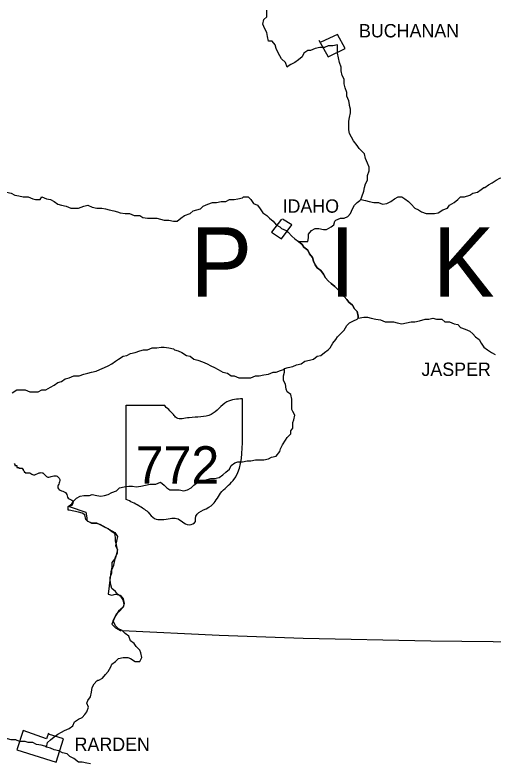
# Model space of a CAD drawing. Extents: x 0 to 40.2, y 0 to 22.
# Drawn here: x 5.119 to 5.818, y 17.238 to 18.331 of the extents above; entities that cross this region are included whole.
import ezdxf

# ---------------------------------------------------------------- set-up
doc = ezdxf.new("R2010")
doc.units = 0
doc.layers.add('Default', color=7, linetype='Continuous')
doc.layers.add('TR_Turning_Path1', color=7, linetype='Continuous')

msp = doc.modelspace()

# ---------------------------------------------------------------- linework, layer by layer
at = {"layer": 'Default'}
msp.add_line((5.2017, 17.6138), (5.1976, 17.6124), dxfattribs=at)
for points in [[(5.5167, 18.2546), (5.514, 18.2614), (5.5085, 18.2669), (5.5058, 18.271), (5.5031, 18.2764), (5.5003, 18.2819), (5.499, 18.2873), (5.4949, 18.2928), (5.4894, 18.2928), (5.4881, 18.2996), (5.4867, 18.3051), (5.484, 18.3105), (5.4812, 18.3173), (5.4826, 18.3241), (5.4867, 18.3282), (5.4867, 18.3351), (5.4867, 18.3378)], [(5.563, 18.2942), (5.5767, 18.2696), (5.6012, 18.2819), (5.5903, 18.3023), (5.5658, 18.2914)], [(5.5903, 18.2873), (5.5835, 18.286), (5.5767, 18.286), (5.5712, 18.2832), (5.5644, 18.2832), (5.5576, 18.2819), (5.5508, 18.2792), (5.5467, 18.2792), (5.5412, 18.2751), (5.5385, 18.2696), (5.533, 18.2655), (5.5276, 18.2614), (5.5221, 18.2587), (5.518, 18.256), (5.5167, 18.2546)], [(5.608, 18.2001), (5.6067, 18.2055), (5.6039, 18.2123), (5.6039, 18.2178), (5.6012, 18.2246), (5.5999, 18.2301), (5.5999, 18.2369), (5.5971, 18.2423), (5.5958, 18.2492), (5.5958, 18.2546), (5.593, 18.2614), (5.5917, 18.2682), (5.5903, 18.2751), (5.5903, 18.2792), (5.5903, 18.286), (5.5903, 18.2873)], [(5.6244, 18.061), (5.6258, 18.0651), (5.6285, 18.0733), (5.6299, 18.0787), (5.6312, 18.0842), (5.6339, 18.0896), (5.6339, 18.0965), (5.6367, 18.1033), (5.6367, 18.1087), (5.6339, 18.1142), (5.6312, 18.121), (5.6299, 18.1278), (5.6258, 18.1319), (5.6217, 18.136), (5.6189, 18.1401), (5.6135, 18.1469), (5.6108, 18.1524), (5.608, 18.1578), (5.6067, 18.1633), (5.6067, 18.1687), (5.6067, 18.1755), (5.608, 18.181), (5.6094, 18.1878), (5.6094, 18.1933), (5.608, 18.1987), (5.608, 18.1987), (5.608, 18.2001)], [(5.8057, 18.0787), (5.8112, 18.0828), (5.8166, 18.0855), (5.8221, 18.0896), (5.8275, 18.0924), (5.833, 18.0937), (5.8398, 18.0937), (5.8453, 18.0937), (5.8507, 18.091), (5.8575, 18.0896), (5.863, 18.091), (5.8657, 18.0924)], [(5.6244, 18.061), (5.6312, 18.0596), (5.6367, 18.0583), (5.6435, 18.0569), (5.6503, 18.0569), (5.6558, 18.0542), (5.6626, 18.0556), (5.668, 18.0583), (5.6735, 18.0624), (5.6789, 18.0651), (5.6844, 18.0651), (5.6885, 18.0624), (5.6939, 18.0583), (5.698, 18.0542), (5.7035, 18.0487), (5.7089, 18.046), (5.713, 18.0433), (5.7198, 18.0406), (5.7267, 18.0406), (5.7321, 18.0406), (5.7376, 18.0419), (5.7444, 18.046), (5.7512, 18.0487), (5.7539, 18.0528), (5.7607, 18.0569), (5.7662, 18.061), (5.7703, 18.0651), (5.7757, 18.0651), (5.7839, 18.0678), (5.788, 18.0706), (5.7948, 18.0719), (5.8003, 18.076), (5.8044, 18.0787), (5.8057, 18.0787), (5.8057, 18.0787)], [(5.0354, 18.0378), (5.0422, 18.0378), (5.0463, 18.0419), (5.0504, 18.046), (5.0572, 18.0487), (5.0613, 18.0542), (5.0668, 18.0583), (5.0722, 18.0624), (5.0763, 18.0665), (5.0804, 18.0706), (5.0872, 18.0733), (5.0927, 18.0746), (5.0995, 18.0733), (5.1063, 18.0719), (5.1131, 18.0706), (5.1186, 18.0678), (5.124, 18.0665), (5.1308, 18.0651), (5.1377, 18.0651), (5.1445, 18.0624), (5.1486, 18.061), (5.1554, 18.061), (5.1554, 18.061)], [(5.1554, 18.061), (5.1581, 18.0651), (5.1649, 18.0624), (5.1704, 18.061), (5.1758, 18.0583), (5.1813, 18.0542), (5.1867, 18.0528), (5.1936, 18.0515), (5.2004, 18.0487), (5.2058, 18.0487), (5.2113, 18.0487), (5.2195, 18.0515), (5.2249, 18.0528), (5.2317, 18.0501), (5.2385, 18.0487), (5.2454, 18.0487), (5.2508, 18.0474), (5.2563, 18.046), (5.2631, 18.0446), (5.2685, 18.0433), (5.2726, 18.0419), (5.2726, 18.0419)], [(5.2726, 18.0419), (5.2795, 18.0406), (5.2863, 18.0406), (5.2931, 18.0378), (5.3013, 18.0378), (5.3054, 18.0351), (5.3122, 18.0337), (5.319, 18.0337), (5.3258, 18.0337), (5.3313, 18.0324), (5.3367, 18.031), (5.3435, 18.031), (5.3503, 18.0296), (5.3558, 18.0296), (5.3613, 18.0337), (5.3667, 18.0378), (5.3749, 18.0406), (5.379, 18.0446), (5.3844, 18.046), (5.3899, 18.0474), (5.394, 18.0515), (5.4008, 18.0542), (5.4076, 18.0569), (5.4131, 18.0569), (5.4199, 18.0583), (5.4267, 18.0583), (5.4322, 18.061), (5.439, 18.061), (5.4444, 18.0624), (5.4512, 18.0637), (5.4526, 18.0651)], [(5.4526, 18.0651), (5.4594, 18.0651), (5.4635, 18.061), (5.4676, 18.0556), (5.4731, 18.0528), (5.4771, 18.0474), (5.4812, 18.0419), (5.4867, 18.0378), (5.4908, 18.0337), (5.4962, 18.0296), (5.5003, 18.0242), (5.5058, 18.0215), (5.5085, 18.0187), (5.5153, 18.016), (5.518, 18.0133), (5.5235, 18.0078), (5.5276, 18.0037), (5.533, 17.9997), (5.533, 17.9997), (5.533, 17.9997)], [(5.5876, 18.031), (5.5944, 18.0337), (5.5999, 18.0337), (5.6053, 18.0365), (5.6094, 18.0406), (5.6121, 18.0474), (5.6149, 18.0528), (5.6189, 18.0569), (5.623, 18.0596), (5.6244, 18.061)], [(5.5085, 18.0324), (5.4935, 18.0133), (5.5085, 18.0037), (5.5235, 18.0242), (5.5099, 18.0324)], [(5.533, 17.9997), (5.5399, 17.9997), (5.5467, 17.9997), (5.548, 18.0051), (5.548, 18.0106), (5.5521, 18.016), (5.5576, 18.0187), (5.563, 18.0187), (5.5699, 18.0174), (5.574, 18.0174), (5.5808, 18.0215), (5.5849, 18.0242), (5.5862, 18.0296), (5.5862, 18.0296), (5.5876, 18.031)], [(5.6203, 17.8879), (5.6203, 17.8892), (5.6203, 17.8906), (5.6189, 17.8974), (5.6149, 17.9015), (5.6121, 17.9069), (5.6067, 17.911), (5.6039, 17.9151), (5.5999, 17.9192), (5.5958, 17.9247), (5.5903, 17.9301), (5.5862, 17.9342), (5.5808, 17.9383), (5.5767, 17.9424), (5.5726, 17.9465), (5.5699, 17.9519), (5.5658, 17.9574), (5.5603, 17.9615), (5.5576, 17.9656), (5.5549, 17.971), (5.5535, 17.9765), (5.5494, 17.9819), (5.5467, 17.9874), (5.5412, 17.9915), (5.5385, 17.9956), (5.533, 17.9997)], [(5.533, 17.9997), (5.5385, 17.9956), (5.5412, 17.9915), (5.5467, 17.9874), (5.5494, 17.9819), (5.5535, 17.9765), (5.5549, 17.971), (5.5576, 17.9656), (5.5603, 17.9615), (5.5658, 17.9574), (5.5699, 17.9519), (5.5726, 17.9465), (5.5767, 17.9424), (5.5808, 17.9383), (5.5862, 17.9342), (5.5903, 17.9301), (5.5958, 17.9247), (5.5999, 17.9192), (5.6039, 17.9151), (5.6067, 17.911), (5.6121, 17.9069), (5.6149, 17.9015), (5.6189, 17.8974), (5.6203, 17.8906), (5.6203, 17.8892), (5.6203, 17.8879)], [(5.6203, 17.8879), (5.6285, 17.8892), (5.6339, 17.8892), (5.6394, 17.8879), (5.6462, 17.8865), (5.653, 17.8851), (5.6598, 17.8824), (5.6653, 17.8824), (5.6721, 17.8824), (5.6776, 17.881), (5.6844, 17.8797), (5.6912, 17.881), (5.698, 17.8824), (5.7035, 17.8824), (5.7103, 17.8838), (5.7185, 17.8865), (5.7239, 17.8865), (5.7294, 17.8879), (5.7348, 17.8865), (5.743, 17.8865), (5.7471, 17.8824), (5.7539, 17.8824), (5.7607, 17.8797), (5.7662, 17.8783), (5.7703, 17.8742), (5.7771, 17.8715), (5.7839, 17.8688), (5.788, 17.8647), (5.7921, 17.8606), (5.7976, 17.8565), (5.8003, 17.851), (5.8044, 17.8456), (5.8098, 17.8415), (5.8153, 17.8374), (5.8207, 17.8347)], [(5.6203, 17.8879), (5.6285, 17.8892), (5.6339, 17.8892), (5.6394, 17.8879), (5.6462, 17.8865), (5.653, 17.8851), (5.6598, 17.8824), (5.6653, 17.8824), (5.6721, 17.8824), (5.6776, 17.881), (5.6844, 17.8797), (5.6912, 17.881), (5.698, 17.8824), (5.7035, 17.8824), (5.7103, 17.8838), (5.7185, 17.8865), (5.7239, 17.8865), (5.7294, 17.8879), (5.7348, 17.8865), (5.743, 17.8865), (5.7471, 17.8824), (5.7539, 17.8824), (5.7607, 17.8797), (5.7662, 17.8783), (5.7703, 17.8742), (5.7771, 17.8715), (5.7839, 17.8688), (5.788, 17.8647), (5.7921, 17.8606), (5.7976, 17.8565), (5.8003, 17.851), (5.8044, 17.8456), (5.8098, 17.8415), (5.8153, 17.8374), (5.8207, 17.8347)], [(5.5126, 17.8142), (5.518, 17.8156), (5.5249, 17.817), (5.5303, 17.8197), (5.5371, 17.821), (5.5426, 17.8251), (5.5494, 17.8265), (5.5549, 17.8279), (5.5603, 17.832), (5.5658, 17.8333), (5.5712, 17.8374), (5.5767, 17.8415), (5.5794, 17.8442), (5.5835, 17.851), (5.5876, 17.8565), (5.5903, 17.8606), (5.5958, 17.866), (5.5999, 17.8701), (5.6039, 17.8769), (5.608, 17.881), (5.6135, 17.8838), (5.6189, 17.8865), (5.6203, 17.8879), (5.6203, 17.8879)], [(5.5126, 17.8142), (5.518, 17.8156), (5.5249, 17.817), (5.5303, 17.8197), (5.5371, 17.821), (5.5426, 17.8251), (5.5494, 17.8265), (5.5549, 17.8279), (5.5603, 17.832), (5.5658, 17.8333), (5.5712, 17.8374), (5.5767, 17.8415), (5.5794, 17.8442), (5.5835, 17.851), (5.5876, 17.8565), (5.5903, 17.8606), (5.5958, 17.866), (5.5999, 17.8701), (5.6039, 17.8769), (5.608, 17.881), (5.6135, 17.8838), (5.6189, 17.8865), (5.6203, 17.8879), (5.6203, 17.8879)], [(5.2058, 17.8033), (5.2126, 17.8033), (5.2195, 17.806), (5.2249, 17.8074), (5.2304, 17.8088), (5.2372, 17.8101), (5.2426, 17.8129), (5.2495, 17.8156), (5.2549, 17.8183), (5.2604, 17.821), (5.2658, 17.8251), (5.2699, 17.8279), (5.2767, 17.832), (5.2822, 17.8333), (5.2876, 17.836), (5.2944, 17.8374), (5.3013, 17.8401), (5.3067, 17.8415), (5.3122, 17.8415), (5.319, 17.8442), (5.3258, 17.8442), (5.3326, 17.8456), (5.3367, 17.8456), (5.3435, 17.8442), (5.3503, 17.8429), (5.3517, 17.8415), (5.3517, 17.8415)], [(5.3517, 17.8415), (5.3572, 17.8401), (5.3626, 17.8374), (5.3694, 17.8333), (5.3749, 17.832), (5.3803, 17.8279), (5.3858, 17.8265), (5.3926, 17.8238), (5.3994, 17.821), (5.4049, 17.8183), (5.4103, 17.8156), (5.4158, 17.8129), (5.4226, 17.8088), (5.4294, 17.8074), (5.4349, 17.8033), (5.439, 17.8033), (5.4458, 17.8006), (5.4512, 17.8006), (5.4581, 17.8006), (5.4635, 17.8006), (5.4703, 17.8033), (5.4758, 17.8033), (5.4826, 17.8047), (5.4894, 17.806), (5.4962, 17.8088), (5.5003, 17.8088), (5.5071, 17.8115), (5.5112, 17.8129), (5.5126, 17.8142)], [(5.5221, 17.7229), (5.5249, 17.727), (5.5249, 17.7352), (5.5262, 17.7392), (5.5276, 17.7461), (5.5249, 17.7515), (5.5235, 17.7542), (5.5235, 17.7624), (5.5235, 17.7692), (5.5221, 17.7761), (5.5167, 17.7801), (5.5153, 17.7842), (5.514, 17.7911), (5.5112, 17.7965), (5.5112, 17.8033), (5.5126, 17.8088), (5.5126, 17.8129), (5.5126, 17.8142)], [(5.1145, 17.7788), (5.1213, 17.7829), (5.1267, 17.7829), (5.1336, 17.7829), (5.1404, 17.7801), (5.1458, 17.7801), (5.1527, 17.7801), (5.1581, 17.7829), (5.1636, 17.7829), (5.1704, 17.787), (5.1758, 17.7897), (5.1813, 17.7938), (5.1867, 17.7951), (5.1922, 17.7992), (5.1976, 17.8006), (5.2045, 17.8033), (5.2058, 17.8033), (5.2058, 17.8033)], [(5.4514, 17.7055), (5.4514, 17.7699)], [(5.2812, 17.6227), (5.2812, 17.7607), (5.3364, 17.7607)], [(5.4635, 17.6792), (5.4703, 17.6806), (5.4758, 17.6806), (5.4826, 17.6806), (5.4894, 17.682), (5.4935, 17.6847), (5.5003, 17.6861), (5.5058, 17.6929), (5.5071, 17.697), (5.5099, 17.7024), (5.514, 17.7092), (5.5167, 17.7133), (5.5221, 17.7188), (5.5221, 17.7215), (5.5221, 17.7229)], [(5.1172, 17.6752), (5.1186, 17.6738), (5.1186, 17.6738), (5.1186, 17.6738), (5.1186, 17.6738), (5.1186, 17.6738), (5.1186, 17.6738), (5.1186, 17.6724), (5.1186, 17.6724), (5.1186, 17.6724), (5.1186, 17.6724), (5.1199, 17.6724), (5.1199, 17.6724), (5.1213, 17.6724), (5.1213, 17.6724), (5.1213, 17.6724), (5.1213, 17.6724), (5.1213, 17.6724), (5.1213, 17.6711), (5.1213, 17.6711), (5.1213, 17.6697), (5.1227, 17.6697), (5.1227, 17.6697), (5.1227, 17.6697), (5.1227, 17.6697), (5.124, 17.6697), (5.124, 17.6697), (5.124, 17.6683), (5.124, 17.6683), (5.1254, 17.6683), (5.1254, 17.6683), (5.1254, 17.6683), (5.1254, 17.6683), (5.1267, 17.6683), (5.1267, 17.6683), (5.1281, 17.6683), (5.1281, 17.6683), (5.1281, 17.6683), (5.1281, 17.6683), (5.1295, 17.6683), (5.1295, 17.6683), (5.1295, 17.6683), (5.1295, 17.6683), (5.1295, 17.6683), (5.1295, 17.667), (5.1295, 17.667), (5.1308, 17.667), (5.1308, 17.667), (5.1308, 17.6656), (5.1308, 17.6656), (5.1308, 17.6656), (5.1308, 17.6656), (5.1308, 17.6656), (5.1308, 17.6656), (5.1308, 17.6656), (5.1308, 17.6656), (5.1322, 17.6643), (5.1322, 17.6643), (5.1322, 17.6643), (5.1322, 17.6643), (5.1322, 17.6643), (5.1322, 17.6629), (5.1336, 17.6629), (5.1336, 17.6615), (5.1349, 17.6615), (5.1349, 17.6615), (5.1349, 17.6615), (5.1349, 17.6615), (5.1349, 17.6615), (5.1349, 17.6615), (5.1349, 17.6615), (5.1349, 17.6615), (5.1363, 17.6615), (5.1377, 17.6615), (5.1377, 17.6615)], [(5.3244, 17.6452), (5.3313, 17.6479), (5.3367, 17.6438), (5.3408, 17.6397), (5.3449, 17.637), (5.3517, 17.637), (5.3585, 17.637), (5.3653, 17.6356), (5.3708, 17.637), (5.3763, 17.6397), (5.3803, 17.6438), (5.3858, 17.6479), (5.3926, 17.6493), (5.3994, 17.652), (5.4049, 17.6533), (5.4103, 17.6533), (5.4172, 17.6547), (5.4226, 17.6588), (5.4267, 17.6629), (5.4322, 17.667), (5.4349, 17.6724), (5.4403, 17.6765), (5.4444, 17.6779), (5.4512, 17.6779), (5.4581, 17.6792), (5.4621, 17.6792), (5.4635, 17.6792)], [(5.1377, 17.6615), (5.1377, 17.6615), (5.1377, 17.6615), (5.1377, 17.6615), (5.1377, 17.6615), (5.1377, 17.6615), (5.139, 17.6615), (5.139, 17.6615), (5.139, 17.6615), (5.139, 17.6615), (5.139, 17.6615), (5.139, 17.6615), (5.139, 17.6615), (5.1404, 17.6615), (5.1404, 17.6615), (5.1404, 17.6615), (5.1404, 17.6615)], [(5.2045, 17.6206), (5.2086, 17.6247), (5.214, 17.6274), (5.2195, 17.6288), (5.2276, 17.6288), (5.2317, 17.6302), (5.2385, 17.6288), (5.244, 17.6274), (5.2495, 17.6288), (5.2549, 17.6302), (5.2604, 17.6329), (5.2672, 17.6356), (5.2713, 17.6397), (5.2781, 17.6411), (5.2849, 17.6424), (5.2904, 17.6424), (5.2958, 17.6411), (5.3026, 17.6424), (5.3094, 17.6438), (5.3163, 17.6452), (5.3231, 17.6452), (5.3244, 17.6452)], [(5.1963, 17.607), (5.1963, 17.6124), (5.2017, 17.6165), (5.2045, 17.6206)], [(5.2604, 17.5197), (5.2631, 17.5265), (5.2645, 17.5334), (5.2658, 17.5388), (5.2685, 17.5443), (5.2685, 17.5497), (5.2672, 17.5565), (5.2658, 17.562), (5.2658, 17.5674), (5.2645, 17.5729), (5.2604, 17.5756), (5.2549, 17.5797), (5.2495, 17.5824), (5.244, 17.5852), (5.2385, 17.5879), (5.2317, 17.5879), (5.2249, 17.5906), (5.2222, 17.5934), (5.2208, 17.6002), (5.2167, 17.6029), (5.2113, 17.6043), (5.2045, 17.6056), (5.1976, 17.607), (5.1963, 17.607), (5.1963, 17.607)], [(5.1976, 17.6124), (5.2222, 17.6043), (5.2236, 17.5961), (5.2236, 17.592), (5.2304, 17.5879), (5.2372, 17.5879), (5.2426, 17.5865), (5.2645, 17.5743), (5.2685, 17.5688), (5.2672, 17.562), (5.2658, 17.5552), (5.2685, 17.5497), (5.2658, 17.5375), (5.2604, 17.5306), (5.2604, 17.5238), (5.259, 17.517), (5.2549, 17.4843), (5.2604, 17.4829), (5.2658, 17.4843), (5.2726, 17.4829), (5.2767, 17.4775), (5.2781, 17.4706), (5.2767, 17.4652), (5.2699, 17.4597), (5.2658, 17.4529), (5.2631, 17.4475), (5.2604, 17.4407), (5.2658, 17.4352), (5.2726, 17.4311), (5.274, 17.4311)], [(5.2617, 17.4447), (5.2645, 17.4502), (5.2672, 17.4556), (5.2713, 17.4597), (5.2767, 17.4652), (5.2781, 17.4693), (5.2767, 17.4761), (5.274, 17.4802), (5.2685, 17.4843), (5.2658, 17.4884), (5.2604, 17.4925), (5.259, 17.4979), (5.2576, 17.5047), (5.2576, 17.5088), (5.2604, 17.5156), (5.2604, 17.5197), (5.2604, 17.5197)], [(5.2413, 17.3588), (5.2467, 17.3616), (5.2508, 17.367), (5.2549, 17.3711), (5.259, 17.3779), (5.2604, 17.382), (5.2658, 17.3861), (5.2699, 17.3902), (5.2767, 17.3916), (5.2835, 17.3916), (5.2876, 17.3902), (5.2944, 17.3861), (5.3013, 17.3861), (5.304, 17.3916), (5.3026, 17.3984), (5.3013, 17.4025), (5.2958, 17.4079), (5.2931, 17.412), (5.2876, 17.4161), (5.2849, 17.4229), (5.2795, 17.427), (5.2754, 17.4311), (5.2699, 17.4338), (5.2658, 17.4379), (5.2631, 17.4434), (5.2631, 17.4434), (5.2617, 17.4447)], [(5.2754, 17.4311), (5.4172, 17.4243), (5.5399, 17.4202), (5.7267, 17.4161), (5.863, 17.4147), (5.9312, 17.412), (6.1207, 17.4038), (6.3988, 17.3888), (6.5093, 17.382), (6.6688, 17.3711), (6.7029, 17.3684)], [(5.1649, 17.2607), (5.1663, 17.2675), (5.1704, 17.2716), (5.1758, 17.2757), (5.1813, 17.2798), (5.1867, 17.2825), (5.1908, 17.2852), (5.1976, 17.2879), (5.2031, 17.292), (5.2058, 17.2975), (5.2113, 17.3016), (5.2167, 17.3043), (5.2208, 17.3084), (5.2236, 17.3125), (5.2263, 17.3193), (5.2236, 17.3248), (5.2249, 17.3289), (5.229, 17.3343), (5.2304, 17.3411), (5.2317, 17.3479), (5.2345, 17.3534), (5.2385, 17.3575), (5.2399, 17.3588), (5.2413, 17.3588)], [(5.1649, 17.2607), (5.1622, 17.262), (5.1567, 17.2634), (5.1499, 17.2648), (5.1445, 17.2675), (5.1377, 17.2675), (5.1336, 17.2689), (5.1254, 17.2689), (5.1199, 17.2716), (5.1131, 17.2716), (5.1077, 17.273), (5.0995, 17.2757), (5.0954, 17.2784), (5.0913, 17.2825), (5.0858, 17.2852), (5.0818, 17.292), (5.0763, 17.2948), (5.0695, 17.2961)], [(5.1677, 17.2811), (5.1649, 17.273), (5.1308, 17.2852), (5.1213, 17.2566), (5.1786, 17.2389), (5.1895, 17.273), (5.1677, 17.2798)], [(5.229, 17.2361), (5.2236, 17.2375), (5.2167, 17.2389), (5.2113, 17.2389), (5.2045, 17.2443), (5.199, 17.247), (5.1949, 17.2511), (5.1881, 17.2525), (5.1826, 17.2552), (5.1758, 17.2566), (5.1704, 17.2593), (5.1649, 17.2607)]]:
    msp.add_lwpolyline(points, dxfattribs=at)
for points in [[(5.4514, 17.7699), (5.4284, 17.7653), (5.4054, 17.7469), (5.3732, 17.7423), (5.3548, 17.7423), (5.3502, 17.7469), (5.3364, 17.7607)], [(5.3134, 17.6043), (5.3226, 17.5951), (5.3456, 17.5951), (5.3548, 17.5951), (5.3732, 17.5859), (5.3824, 17.5905), (5.3824, 17.5951), (5.4054, 17.6135), (5.4192, 17.6319), (5.4376, 17.6503), (5.4514, 17.7055)], [(5.1404, 17.6615), (5.1458, 17.6588), (5.154, 17.6615), (5.1595, 17.6615), (5.1649, 17.6561), (5.1717, 17.6561), (5.1786, 17.6574), (5.184, 17.652), (5.1826, 17.6452), (5.1813, 17.6397), (5.1867, 17.6356), (5.1936, 17.6315), (5.1963, 17.6247), (5.2031, 17.6206), (5.2017, 17.6138)], [(5.3134, 17.6043), (5.2996, 17.6135), (5.2812, 17.6227)]]:
    msp.add_spline(points, degree=3, dxfattribs=at)

# ---------------------------------------------------------------- texts
for s, height, p in [('BUCHANAN', 0.0195, (5.6217, 18.2982)), ('IDAHO', 0.0195, (5.5099, 18.0419)), ('JASPER', 0.0195, (5.713, 17.8033)), ('772', 0.05486, (5.295, 17.6457)), ('RARDEN', 0.0195, (5.2058, 17.2552))]:
    msp.add_text(s, height=height, dxfattribs=at).set_placement(p)
at = {"layer": 'TR_Turning_Path1'}
msp.add_text('P   I   K   E', height=0.101489, dxfattribs=at).set_placement((5.3749, 17.9192))

doc.saveas('drawing.dxf')
